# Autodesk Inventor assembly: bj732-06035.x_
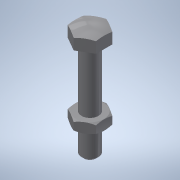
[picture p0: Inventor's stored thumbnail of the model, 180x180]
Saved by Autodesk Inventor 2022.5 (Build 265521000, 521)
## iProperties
Part Number: bj732-06035.x_
Material: 一般
Document SubType Name: Assembly
Designer: ImaoCorp
Sending System: SOLIDWORKS 2017-2017317
MC: AMD64
MC_MODEL: Intel64 Family 6 Model 60 Stepping 3, GenuineIntel
OS: Windows_NT
FRU: Parasolid Version 29.0, build 201,  4-17-2017
FORMAT: text
GUISE: transmit
KEY: bj732-06035
FILE: bj732-06035.x_t
DATE: Fri Mar 15 10:11:10 2019
Author: ImaoCorp
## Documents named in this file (3)
- X:\14_SW2022-Inv2022\00_全2023-1023新製品(TCC)まで\b\bj732-06035\BJ732-06035.iam
- X:\14_SW2022-Inv2022\00_全2023-1023新製品(TCC)まで\b\bj732-06035\bj732-06035_01.ipt
- X:\14_SW2022-Inv2022\00_全2023-1023新製品(TCC)まで\b\bj732-06035\bj732-06035_02.ipt
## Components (2 placed, 2 different names)
1. bj732-06035_01
2. bj732-06035_02
